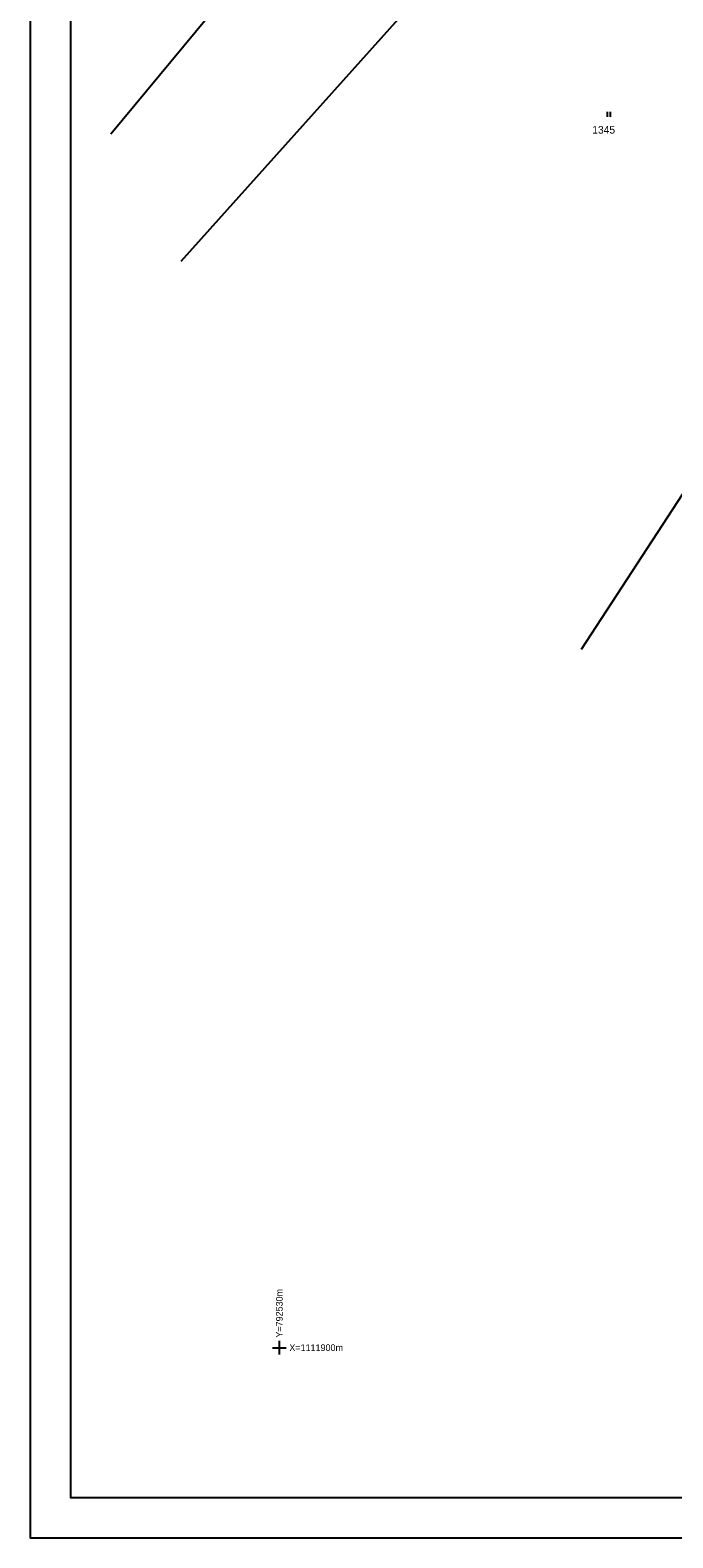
# Model space of a CAD drawing. Extents: x -792549 to -792339, y -1111914 to -1111617.
# Drawn here: x -792548.6 to -792500.7, y -1111914.2 to -1111801.9 of the extents above; entities that cross this region are included whole.
import ezdxf

# ---------------------------------------------------------------- set-up
doc = ezdxf.new("R2010")
doc.units = 0
for name, color, linetype in [('Vrstva 1', 7, 'Continuous'), ('Vrstva 24', 7, 'Continuous'), ('Vrstva 41', 7, 'Continuous'), ('Vrstva 42', 7, 'Continuous'), ('Vrstva 45', 7, 'Continuous'), ('Vrstva 60', 7, 'Continuous')]:
    doc.layers.add(name, color=color, linetype=linetype)

# ---------------------------------------------------------------- blocks, each defined once
blk = doc.blocks.new('3$0600')
at = {"layer": 'Vrstva 1'}
for p, q in [((-5, 15), (-5, 0)), ((5, 0), (5, 15))]:
    blk.add_line(p, q, dxfattribs=at)
blk = doc.blocks.new('$408')
at = {"layer": 'Vrstva 1'}
for p, q in [((-20, 0), (20, 0)), ((0, 20), (0, -20))]:
    blk.add_line(p, q, dxfattribs=at)

msp = doc.modelspace()

# ---------------------------------------------------------------- linework, layer by layer
at = {"layer": 'Vrstva 24'}
msp.add_lwpolyline([(-792545.56, -1111620.16), (-792545.56, -1111911.16), (-792341.56, -1111911.16), (-792341.56, -1111620.16)], close=True, dxfattribs=at)
at = {"layer": 'Vrstva 41'}
for points in [[(-792537.3, -1111819.07), (-792509.03, -1111787.52), (-792494.7, -1111767.15), (-792487.93, -1111755.84), (-792488.57, -1111751.6), (-792481.63, -1111739.54), (-792474.4, -1111729.01), (-792471.44, -1111725.75), (-792468.11, -1111720.8), (-792469.49, -1111708.06)], [(-792480.39, -1111721.44), (-792511.65, -1111770.81), (-792516.32, -1111777.99), (-792542.55, -1111809.62)], [(-792481.82, -1111799.75), (-792488.22, -1111815.61), (-792496.94, -1111831.79), (-792507.51, -1111847.99)]]:
    msp.add_lwpolyline(points, dxfattribs=at)
at = {"layer": 'Vrstva 60'}
msp.add_lwpolyline([(-792548.56, -1111617.16), (-792548.56, -1111914.16), (-792338.56, -1111914.16), (-792338.56, -1111617.16), (-792548.56, -1111617.16)], dxfattribs=at)

# ---------------------------------------------------------------- block references
at = {"layer": 'Vrstva 42', "xscale": 0.025000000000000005, "yscale": 0.025, "rotation": -0.6375094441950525}
msp.add_blockref('3$0600', (-792505.45, -1111808.33), dxfattribs=at)
at = {"layer": 'Vrstva 45', "xscale": 0.025, "yscale": 0.025000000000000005}
msp.add_blockref('$408', (-792530, -1111900), dxfattribs=at)

# ---------------------------------------------------------------- texts
at = {"layer": 'Vrstva 42'}
msp.add_text('1345', height=0.57, dxfattribs=at).set_placement((-792506.68, -1111809.57))
at = {"layer": 'Vrstva 45'}
msp.add_text('Y=792530m', height=0.5, rotation=90.012, dxfattribs=at).set_placement((-792529.75, -1111899.25))
msp.add_text('X=1111900m', height=0.5, dxfattribs=at).set_placement((-792529.25, -1111900.25))

doc.saveas('drawing.dxf')
